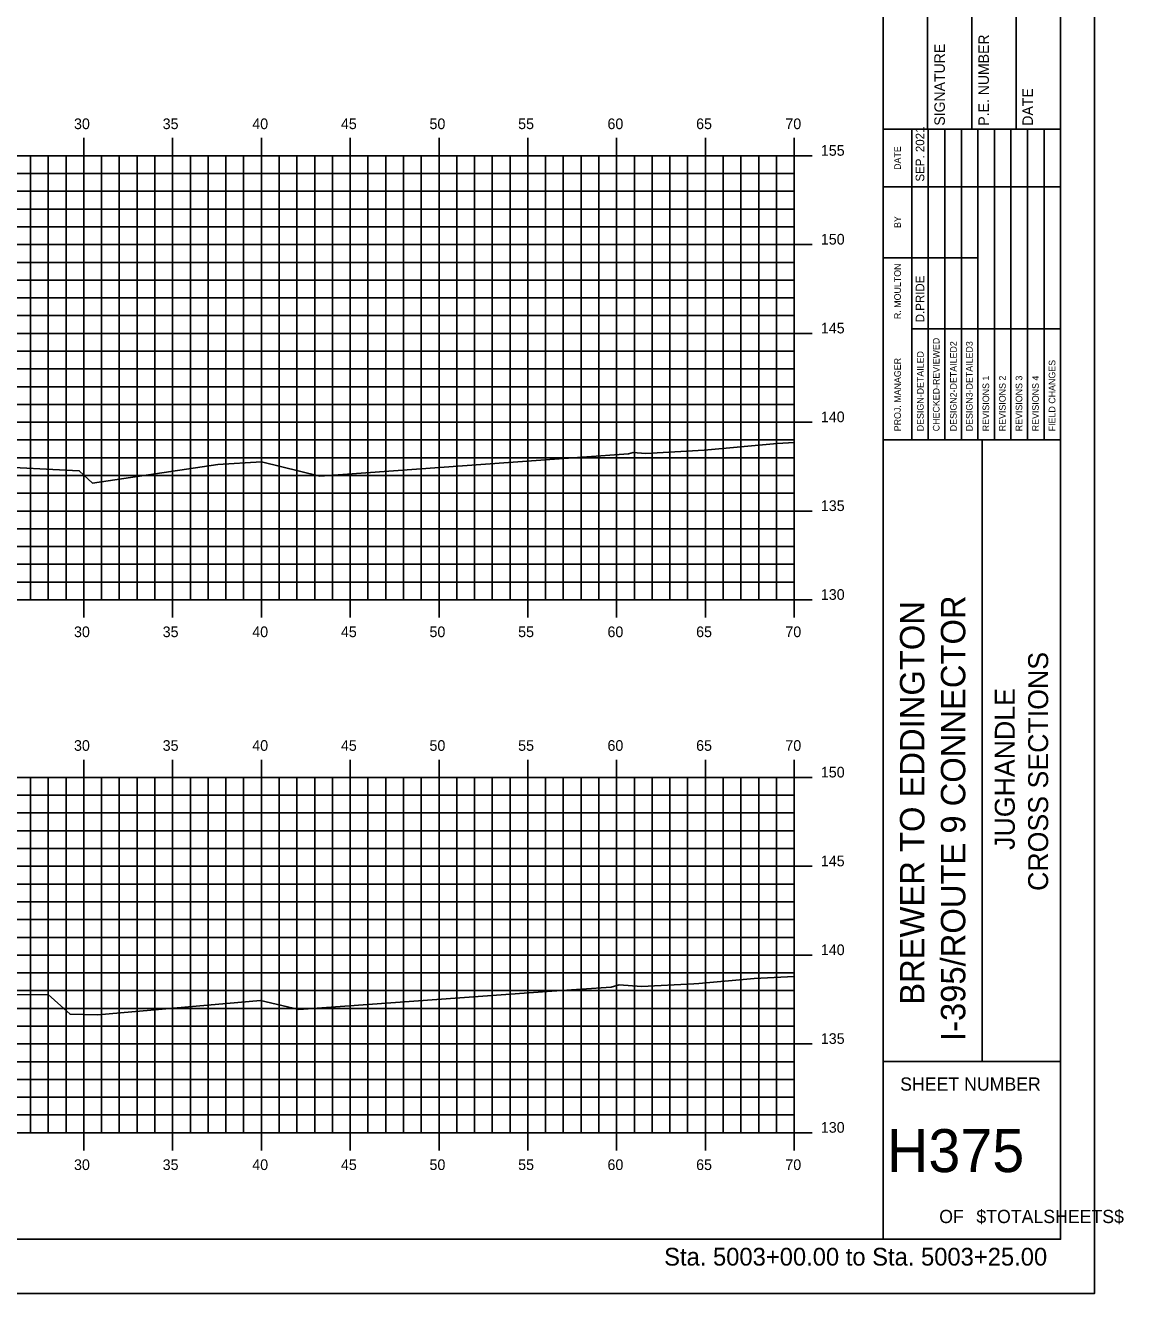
# Model space of a CAD drawing. Extents: x 851639 to 851810, y 365876 to 365986.
# Drawn here: x 851748.4 to 851810.2, y 365875.8 to 365947.2 of the extents above; entities that cross this region are included whole.
import ezdxf

# ---------------------------------------------------------------- set-up
doc = ezdxf.new("R2010")
doc.units = 0
for name, color, linetype in [('BORDER', 7, 'Continuous'), ('H_V ANNOTATION', 7, 'Continuous'), ('MAJOR', 7, 'Continuous'), ('MINOR', 7, 'Continuous'), ('PLOT BOUNDARY', 7, 'Continuous'), ('S_Roadway_Centerline', 7, 'Continuous')]:
    doc.layers.add(name, color=color, linetype=linetype)

msp = doc.modelspace()

# ---------------------------------------------------------------- linework, layer by layer
at = {"layer": 'BORDER'}
for p, q in [((851796.655, 365878.833), (851796.655, 365983.833)), ((851799.155, 365941.336), (851799.155, 365949.984)), ((851801.655, 365941.336), (851801.655, 365949.984)), ((851804.155, 365941.336), (851804.155, 365949.984)), ((851796.655, 365941.336), (851806.655, 365941.336)), ((851796.655, 365923.836), (851806.655, 365923.836)), ((851802.246, 365888.836), (851802.246, 365923.836)), ((851796.655, 365888.836), (851806.655, 365888.836))]:
    msp.add_line(p, q, dxfattribs=at)
msp.add_lwpolyline([(851646.655, 365878.833), (851806.655, 365878.833), (851806.655, 365983.833), (851646.655, 365983.833)], close=True, dxfattribs=at)
for points in [[(851798.27, 365938.086), (851798.27, 365941.336)], [(851799.203, 365923.839), (851799.203, 365941.336)], [(851800.134, 365941.336), (851800.134, 365923.839)], [(851801.066, 365923.839), (851801.066, 365941.336)], [(851801.998, 365923.839), (851801.998, 365941.336)], [(851802.929, 365923.839), (851802.929, 365941.336)], [(851803.861, 365923.839), (851803.861, 365941.336)], [(851804.793, 365923.839), (851804.793, 365941.336)], [(851805.724, 365923.839), (851805.724, 365941.336)], [(851798.271, 365923.839), (851798.271, 365940.63)], [(851796.655, 365938.086), (851806.655, 365938.086)], [(851796.655, 365934.086), (851798.271, 365934.086)], [(851798.27, 365934.086), (851801.997, 365934.086)], [(851798.27, 365930.086), (851806.655, 365930.086)]]:
    msp.add_lwpolyline(points, dxfattribs=at)
at = {"layer": 'MAJOR'}
for p, q in [((851751.655, 365940.835), (851751.655, 365939.833)), ((851756.655, 365940.835), (851756.655, 365939.833)), ((851761.655, 365940.835), (851761.655, 365939.833)), ((851766.655, 365940.835), (851766.655, 365939.833)), ((851771.655, 365940.835), (851771.655, 365939.833)), ((851776.655, 365940.835), (851776.655, 365939.833)), ((851781.655, 365940.835), (851781.655, 365939.833)), ((851786.655, 365940.835), (851786.655, 365939.833)), ((851791.655, 365940.835), (851791.655, 365939.833)), ((851651.655, 365939.833), (851791.655, 365939.833)), ((851651.655, 365939.833), (851791.655, 365939.833)), ((851751.655, 365914.833), (851751.655, 365939.833)), ((851756.655, 365914.833), (851756.655, 365939.833)), ((851761.655, 365914.833), (851761.655, 365939.833)), ((851766.655, 365914.833), (851766.655, 365939.833)), ((851771.655, 365914.833), (851771.655, 365939.833)), ((851776.655, 365914.833), (851776.655, 365939.833)), ((851781.655, 365914.833), (851781.655, 365939.833)), ((851786.655, 365914.833), (851786.655, 365939.833)), ((851792.657, 365939.833), (851790.653, 365939.833)), ((851791.655, 365914.833), (851791.655, 365939.833)), ((851791.655, 365914.833), (851791.655, 365939.833)), ((851651.655, 365934.833), (851791.655, 365934.833)), ((851792.657, 365934.833), (851790.653, 365934.833)), ((851651.655, 365929.833), (851791.655, 365929.833)), ((851792.657, 365929.833), (851790.653, 365929.833)), ((851651.655, 365924.833), (851791.655, 365924.833)), ((851792.657, 365924.833), (851790.653, 365924.833)), ((851651.655, 365919.833), (851791.655, 365919.833)), ((851792.657, 365919.833), (851790.653, 365919.833)), ((851651.655, 365914.833), (851791.655, 365914.833)), ((851651.655, 365914.833), (851791.655, 365914.833)), ((851751.655, 365913.831), (851751.655, 365914.833)), ((851756.655, 365913.831), (851756.655, 365914.833)), ((851761.655, 365913.831), (851761.655, 365914.833)), ((851766.655, 365913.831), (851766.655, 365914.833)), ((851771.655, 365913.831), (851771.655, 365914.833)), ((851776.655, 365913.831), (851776.655, 365914.833)), ((851781.655, 365913.831), (851781.655, 365914.833)), ((851786.655, 365913.831), (851786.655, 365914.833)), ((851792.657, 365914.833), (851790.653, 365914.833)), ((851791.655, 365913.831), (851791.655, 365914.833)), ((851751.655, 365905.835), (851751.655, 365904.833)), ((851756.655, 365905.835), (851756.655, 365904.833)), ((851761.655, 365905.835), (851761.655, 365904.833)), ((851766.655, 365905.835), (851766.655, 365904.833)), ((851771.655, 365905.835), (851771.655, 365904.833)), ((851776.655, 365905.835), (851776.655, 365904.833)), ((851781.655, 365905.835), (851781.655, 365904.833)), ((851786.655, 365905.835), (851786.655, 365904.833)), ((851791.655, 365905.835), (851791.655, 365904.833)), ((851651.655, 365904.833), (851791.655, 365904.833)), ((851651.655, 365904.833), (851791.655, 365904.833)), ((851751.655, 365884.833), (851751.655, 365904.833)), ((851756.655, 365884.833), (851756.655, 365904.833)), ((851761.655, 365884.833), (851761.655, 365904.833)), ((851766.655, 365884.833), (851766.655, 365904.833)), ((851771.655, 365884.833), (851771.655, 365904.833)), ((851776.655, 365884.833), (851776.655, 365904.833)), ((851781.655, 365884.833), (851781.655, 365904.833)), ((851786.655, 365884.833), (851786.655, 365904.833)), ((851792.657, 365904.833), (851790.653, 365904.833)), ((851791.655, 365884.833), (851791.655, 365904.833)), ((851791.655, 365884.833), (851791.655, 365904.833)), ((851651.655, 365899.833), (851791.655, 365899.833)), ((851792.657, 365899.833), (851790.653, 365899.833)), ((851651.655, 365894.833), (851791.655, 365894.833)), ((851792.657, 365894.833), (851790.653, 365894.833)), ((851651.655, 365889.833), (851791.655, 365889.833)), ((851792.657, 365889.833), (851790.653, 365889.833)), ((851651.655, 365884.833), (851791.655, 365884.833)), ((851651.655, 365884.833), (851791.655, 365884.833)), ((851751.655, 365883.831), (851751.655, 365884.833)), ((851756.655, 365883.831), (851756.655, 365884.833)), ((851761.655, 365883.831), (851761.655, 365884.833)), ((851766.655, 365883.831), (851766.655, 365884.833)), ((851771.655, 365883.831), (851771.655, 365884.833)), ((851776.655, 365883.831), (851776.655, 365884.833)), ((851781.655, 365883.831), (851781.655, 365884.833)), ((851786.655, 365883.831), (851786.655, 365884.833)), ((851792.657, 365884.833), (851790.653, 365884.833)), ((851791.655, 365883.831), (851791.655, 365884.833))]:
    msp.add_line(p, q, dxfattribs=at)
at = {"layer": 'MINOR'}
for p, q in [((851748.655, 365914.833), (851748.655, 365939.833)), ((851749.655, 365914.833), (851749.655, 365939.833)), ((851750.655, 365914.833), (851750.655, 365939.833)), ((851752.655, 365914.833), (851752.655, 365939.833)), ((851753.655, 365914.833), (851753.655, 365939.833)), ((851754.655, 365914.833), (851754.655, 365939.833)), ((851755.655, 365914.833), (851755.655, 365939.833)), ((851757.655, 365914.833), (851757.655, 365939.833)), ((851758.655, 365914.833), (851758.655, 365939.833)), ((851759.655, 365914.833), (851759.655, 365939.833)), ((851760.655, 365914.833), (851760.655, 365939.833)), ((851762.655, 365914.833), (851762.655, 365939.833)), ((851763.655, 365914.833), (851763.655, 365939.833)), ((851764.655, 365914.833), (851764.655, 365939.833)), ((851765.655, 365914.833), (851765.655, 365939.833)), ((851767.655, 365914.833), (851767.655, 365939.833)), ((851768.655, 365914.833), (851768.655, 365939.833)), ((851769.655, 365914.833), (851769.655, 365939.833)), ((851770.655, 365914.833), (851770.655, 365939.833)), ((851772.655, 365914.833), (851772.655, 365939.833)), ((851773.655, 365914.833), (851773.655, 365939.833)), ((851774.655, 365914.833), (851774.655, 365939.833)), ((851775.655, 365914.833), (851775.655, 365939.833)), ((851777.655, 365914.833), (851777.655, 365939.833)), ((851778.655, 365914.833), (851778.655, 365939.833)), ((851779.655, 365914.833), (851779.655, 365939.833)), ((851780.655, 365914.833), (851780.655, 365939.833)), ((851782.655, 365914.833), (851782.655, 365939.833)), ((851783.655, 365914.833), (851783.655, 365939.833)), ((851784.655, 365914.833), (851784.655, 365939.833)), ((851785.655, 365914.833), (851785.655, 365939.833)), ((851787.655, 365914.833), (851787.655, 365939.833)), ((851788.655, 365914.833), (851788.655, 365939.833)), ((851789.655, 365914.833), (851789.655, 365939.833)), ((851790.655, 365914.833), (851790.655, 365939.833)), ((851651.655, 365938.833), (851791.655, 365938.833)), ((851791.655, 365938.833), (851790.653, 365938.833)), ((851651.655, 365937.833), (851791.655, 365937.833)), ((851791.655, 365937.833), (851790.653, 365937.833)), ((851651.655, 365936.833), (851791.655, 365936.833)), ((851791.655, 365936.833), (851790.653, 365936.833)), ((851651.655, 365935.833), (851791.655, 365935.833)), ((851791.655, 365935.833), (851790.653, 365935.833)), ((851651.655, 365933.833), (851791.655, 365933.833)), ((851791.655, 365933.833), (851790.653, 365933.833)), ((851651.655, 365932.833), (851791.655, 365932.833)), ((851791.655, 365932.833), (851790.653, 365932.833)), ((851651.655, 365931.833), (851791.655, 365931.833)), ((851791.655, 365931.833), (851790.653, 365931.833)), ((851651.655, 365930.833), (851791.655, 365930.833)), ((851791.655, 365930.833), (851790.653, 365930.833)), ((851651.655, 365928.833), (851791.655, 365928.833)), ((851791.655, 365928.833), (851790.653, 365928.833)), ((851651.655, 365927.833), (851791.655, 365927.833)), ((851791.655, 365927.833), (851790.653, 365927.833)), ((851651.655, 365926.833), (851791.655, 365926.833)), ((851791.655, 365926.833), (851790.653, 365926.833)), ((851651.655, 365925.833), (851791.655, 365925.833)), ((851791.655, 365925.833), (851790.653, 365925.833)), ((851651.655, 365923.833), (851791.655, 365923.833)), ((851791.655, 365923.833), (851790.653, 365923.833)), ((851651.655, 365922.833), (851791.655, 365922.833)), ((851791.655, 365922.833), (851790.653, 365922.833)), ((851651.655, 365921.833), (851791.655, 365921.833)), ((851791.655, 365921.833), (851790.653, 365921.833)), ((851651.655, 365920.833), (851791.655, 365920.833)), ((851791.655, 365920.833), (851790.653, 365920.833)), ((851651.655, 365918.833), (851791.655, 365918.833)), ((851791.655, 365918.833), (851790.653, 365918.833)), ((851651.655, 365917.833), (851791.655, 365917.833)), ((851791.655, 365917.833), (851790.653, 365917.833)), ((851651.655, 365916.833), (851791.655, 365916.833)), ((851791.655, 365916.833), (851790.653, 365916.833)), ((851651.655, 365915.833), (851791.655, 365915.833)), ((851791.655, 365915.833), (851790.653, 365915.833)), ((851748.655, 365884.833), (851748.655, 365904.833)), ((851749.655, 365884.833), (851749.655, 365904.833)), ((851750.655, 365884.833), (851750.655, 365904.833)), ((851752.655, 365884.833), (851752.655, 365904.833)), ((851753.655, 365884.833), (851753.655, 365904.833)), ((851754.655, 365884.833), (851754.655, 365904.833)), ((851755.655, 365884.833), (851755.655, 365904.833)), ((851757.655, 365884.833), (851757.655, 365904.833)), ((851758.655, 365884.833), (851758.655, 365904.833)), ((851759.655, 365884.833), (851759.655, 365904.833)), ((851760.655, 365884.833), (851760.655, 365904.833)), ((851762.655, 365884.833), (851762.655, 365904.833)), ((851763.655, 365884.833), (851763.655, 365904.833)), ((851764.655, 365884.833), (851764.655, 365904.833)), ((851765.655, 365884.833), (851765.655, 365904.833)), ((851767.655, 365884.833), (851767.655, 365904.833)), ((851768.655, 365884.833), (851768.655, 365904.833)), ((851769.655, 365884.833), (851769.655, 365904.833)), ((851770.655, 365884.833), (851770.655, 365904.833)), ((851772.655, 365884.833), (851772.655, 365904.833)), ((851773.655, 365884.833), (851773.655, 365904.833)), ((851774.655, 365884.833), (851774.655, 365904.833)), ((851775.655, 365884.833), (851775.655, 365904.833)), ((851777.655, 365884.833), (851777.655, 365904.833)), ((851778.655, 365884.833), (851778.655, 365904.833)), ((851779.655, 365884.833), (851779.655, 365904.833)), ((851780.655, 365884.833), (851780.655, 365904.833)), ((851782.655, 365884.833), (851782.655, 365904.833)), ((851783.655, 365884.833), (851783.655, 365904.833)), ((851784.655, 365884.833), (851784.655, 365904.833)), ((851785.655, 365884.833), (851785.655, 365904.833)), ((851787.655, 365884.833), (851787.655, 365904.833)), ((851788.655, 365884.833), (851788.655, 365904.833)), ((851789.655, 365884.833), (851789.655, 365904.833)), ((851790.655, 365884.833), (851790.655, 365904.833)), ((851651.655, 365903.833), (851791.655, 365903.833)), ((851791.655, 365903.833), (851790.653, 365903.833)), ((851651.655, 365902.833), (851791.655, 365902.833)), ((851791.655, 365902.833), (851790.653, 365902.833)), ((851651.655, 365901.833), (851791.655, 365901.833)), ((851791.655, 365901.833), (851790.653, 365901.833)), ((851651.655, 365900.833), (851791.655, 365900.833)), ((851791.655, 365900.833), (851790.653, 365900.833)), ((851651.655, 365898.833), (851791.655, 365898.833)), ((851791.655, 365898.833), (851790.653, 365898.833)), ((851651.655, 365897.833), (851791.655, 365897.833)), ((851791.655, 365897.833), (851790.653, 365897.833)), ((851651.655, 365896.833), (851791.655, 365896.833)), ((851791.655, 365896.833), (851790.653, 365896.833)), ((851651.655, 365895.833), (851791.655, 365895.833)), ((851791.655, 365895.833), (851790.653, 365895.833)), ((851651.655, 365893.833), (851791.655, 365893.833)), ((851791.655, 365893.833), (851790.653, 365893.833)), ((851651.655, 365892.833), (851791.655, 365892.833)), ((851791.655, 365892.833), (851790.653, 365892.833)), ((851651.655, 365891.833), (851791.655, 365891.833)), ((851791.655, 365891.833), (851790.653, 365891.833)), ((851651.655, 365890.833), (851791.655, 365890.833)), ((851791.655, 365890.833), (851790.653, 365890.833)), ((851651.655, 365888.833), (851791.655, 365888.833)), ((851791.655, 365888.833), (851790.653, 365888.833)), ((851651.655, 365887.833), (851791.655, 365887.833)), ((851791.655, 365887.833), (851790.653, 365887.833)), ((851651.655, 365886.833), (851791.655, 365886.833)), ((851791.655, 365886.833), (851790.653, 365886.833)), ((851651.655, 365885.833), (851791.655, 365885.833)), ((851791.655, 365885.833), (851790.653, 365885.833))]:
    msp.add_line(p, q, dxfattribs=at)
at = {"layer": 'PLOT BOUNDARY'}
msp.add_lwpolyline([(851638.562, 365875.774), (851808.562, 365875.774), (851808.562, 365985.774), (851638.562, 365985.774)], close=True, dxfattribs=at)
at = {"layer": 'S_Roadway_Centerline'}
for points in [[(851746.206, 365922.359), (851751.4, 365922.097), (851752.146, 365921.407), (851759.206, 365922.459), (851761.658, 365922.605), (851764.949, 365921.795), (851779.72, 365922.874), (851782.325, 365923.056), (851782.596, 365923.13), (851783.29, 365923.08), (851786.584, 365923.259), (851786.791, 365923.278), (851790.704, 365923.64), (851791.655, 365923.698)], [(851742.245, 365892.534), (851749.65, 365892.612), (851750.882, 365891.499), (851752.451, 365891.474), (851761.602, 365892.277), (851763.756, 365891.772), (851778.008, 365892.802), (851781.355, 365893.03), (851781.8, 365893.155), (851783.06, 365893.069), (851785.996, 365893.213), (851786.282, 365893.238), (851789.399, 365893.509), (851791.655, 365893.634)]]:
    msp.add_lwpolyline(points, dxfattribs=at)

# ---------------------------------------------------------------- texts
at = {"layer": 'BORDER'}
for s, height, p in [('SIGNATURE', 0.5906, (851800.136, 365941.528)), ('P.E. NUMBER', 0.59055, (851802.616, 365941.528)), ('DATE', 0.5906, (851805.096, 365941.528)), ('SEP. 2021', 0.4845, (851798.978, 365938.382)), ('DATE', 0.3714, (851797.659, 365939.042)), ('BY', 0.3714, (851797.659, 365935.771)), ('R. MOULTON', 0.3727, (851797.659, 365930.639)), ('D.PRIDE', 0.4845, (851798.978, 365930.459)), ('CHECKED-REVIEWED', 0.37275, (851799.836, 365924.324)), ('DESIGN2-DETAILED2', 0.37275, (851800.805, 365924.324)), ('DESIGN3-DETAILED3', 0.37275, (851801.7, 365924.324)), ('PROJ. MANAGER', 0.37275, (851797.659, 365924.324)), ('DESIGN-DETAILED', 0.37275, (851798.942, 365924.324)), ('FIELD CHANGES', 0.37275, (851806.358, 365924.324)), ('REVISIONS 1', 0.37275, (851802.631, 365924.324)), ('REVISIONS 2', 0.37275, (851803.563, 365924.324)), ('REVISIONS 3', 0.37275, (851804.495, 365924.324)), ('REVISIONS 4', 0.37275, (851805.426, 365924.324)), ('I-395/ROUTE 9 CONNECTOR', 1.37787, (851801.29, 365889.998)), ('BREWER TO EDDINGTON', 1.37787, (851798.989, 365892.038)), ('CROSS SECTIONS', 1.125, (851805.953, 365898.444)), ('JUGHANDLE', 1.125, (851804.074, 365900.756))]:
    msp.add_text(s, height=height, rotation=90, dxfattribs=at).set_placement(p)
for s, height, p in [('SHEET NUMBER', 0.74527, (851797.621, 365887.2)), ('H375', 2.4194, (851796.875, 365882.616)), ('OF', 0.7453, (851799.822, 365879.746)), ('$TOTALSHEETS$', 0.74527, (851801.912, 365879.746))]:
    msp.add_text(s, height=height, dxfattribs=at).set_placement(p)
at = {"layer": 'H_V ANNOTATION'}
for s, height, p in [('30', 0.6, (851751.104, 365941.333)), ('35', 0.6, (851756.096, 365941.333)), ('40', 0.6, (851761.141, 365941.333)), ('45', 0.6, (851766.133, 365941.333)), ('50', 0.6, (851771.12, 365941.333)), ('55', 0.6, (851776.112, 365941.333)), ('60', 0.6, (851781.141, 365941.333)), ('65', 0.6, (851786.133, 365941.333)), ('70', 0.6, (851791.157, 365941.333)), ('155', 0.6, (851793.155, 365939.833)), ('150', 0.6, (851793.155, 365934.833)), ('145', 0.6, (851793.155, 365929.833)), ('140', 0.6, (851793.155, 365924.833)), ('135', 0.6, (851793.155, 365919.833)), ('130', 0.6, (851793.155, 365914.833)), ('30', 0.6, (851751.104, 365912.733)), ('35', 0.6, (851756.096, 365912.733)), ('40', 0.6, (851761.141, 365912.733)), ('45', 0.6, (851766.133, 365912.733)), ('50', 0.6, (851771.12, 365912.733)), ('55', 0.6, (851776.112, 365912.733)), ('60', 0.6, (851781.141, 365912.733)), ('65', 0.6, (851786.133, 365912.733)), ('70', 0.6, (851791.157, 365912.733)), ('30', 0.6, (851751.104, 365906.333)), ('35', 0.6, (851756.096, 365906.333)), ('40', 0.6, (851761.141, 365906.333)), ('45', 0.6, (851766.133, 365906.333)), ('50', 0.6, (851771.12, 365906.333)), ('55', 0.6, (851776.112, 365906.333)), ('60', 0.6, (851781.141, 365906.333)), ('65', 0.6, (851786.133, 365906.333)), ('70', 0.6, (851791.157, 365906.333)), ('150', 0.6, (851793.155, 365904.833)), ('145', 0.6, (851793.155, 365899.833)), ('140', 0.6, (851793.155, 365894.833)), ('135', 0.6, (851793.155, 365889.833)), ('130', 0.6, (851793.155, 365884.833)), ('30', 0.6, (851751.104, 365882.733)), ('35', 0.6, (851756.096, 365882.733)), ('40', 0.6, (851761.141, 365882.733)), ('45', 0.6, (851766.133, 365882.733)), ('50', 0.6, (851771.12, 365882.733)), ('55', 0.6, (851776.112, 365882.733)), ('60', 0.6, (851781.141, 365882.733)), ('65', 0.6, (851786.133, 365882.733)), ('70', 0.6, (851791.157, 365882.733)), ('Sta. 5003+00.00 to Sta. 5003+25.00', 1.0002, (851784.331, 365877.353))]:
    msp.add_text(s, height=height, dxfattribs=at).set_placement(p)

doc.saveas('drawing.dxf')
